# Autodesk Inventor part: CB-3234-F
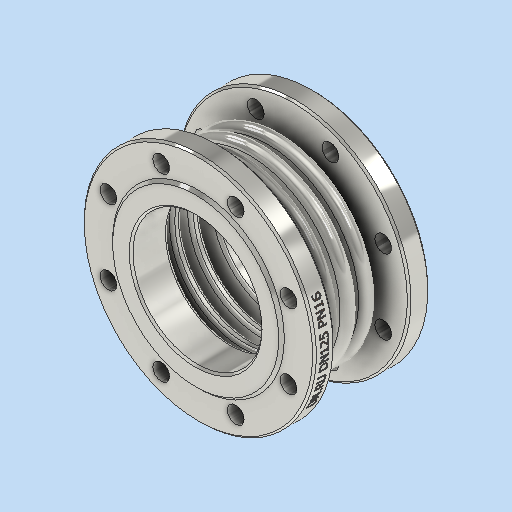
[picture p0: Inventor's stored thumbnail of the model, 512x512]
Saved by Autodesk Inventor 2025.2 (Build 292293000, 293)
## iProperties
Company: DN.RU
Created: 2026-04
Part Number: CB-3234-F
Material: Типовые
Document SubType Name: Modeling
Designer: DN.RU
Density: 6.05543 g/cm^3
Appearance: По умолчанию
Description: D140-02117
Mass: 10500 g
Surface Area: 4722.2 cm^2
Volume: 1733.98 cm^3
Author: DN.RU
Title: Компенсатор сильфонный осевой DN.ru Ду125 Ру16
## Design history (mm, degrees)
sketch "Эскиз1"
  geometry: L1 (0, 0)-(0, -65); L2 (77.5, -65)-(77.5, 0); L3 (77.5, 0)-(0, 0); L4 (77.5, 0)-(77.5, 0); L5 (57.5, 0)-(97.5, 0); L6 (57.5, -7)-(97.5, -7); L7 (97.5, 7)-(57.5, 7); L8 (97.5, -5)-(57.5, -5); L9 (57.5, 5)-(97.5, 5); L10 (97.5, -13)-(57.5, -13); L11 (57.5, -15)-(97.5, -15); L12 (57.5, -20)-(97.5, -20); L13 (57.5, -27)-(97.5, -27); L14 (97.5, -25)-(57.5, -25); L15 (0, -65)-(77.5, -65); L16 (77.5, -65)-(69.5, -65); L17 (69.5, -65)-(69.5, -25); L18 (77.5, -15)-(75.5, -15); L19 (75.5, -15)-(75.5, -5); L20 (77.5, 5)-(75.5, 5); L21 (75.5, 5)-(75.5, 0); L22 (0, -65)-(0, -40); L23 (0, -40)-(125, -40); L24 (125, -40)-(125, -65); L25 (125, -65)-(0, -65); L26 (77.5, -40)-(77.5, -55); L27 (77.5, -55)-(81.5, -55); L28 (81.5, -55)-(81.5, -40); L29 (81.5, -40)-(77.5, -40); L30 (77.5, 0)-(104.5, 0); A1 r 7 centre (57.5, 0) between (57.5, 7) and (57.5, -7); A2 r 7 centre (97.5, 0) between (97.5, -7) and (97.5, 7); A3 r 5 centre (57.5, 0) between (57.5, 5) and (57.5, -5); A4 r 5 centre (97.5, 0) between (97.5, -5) and (97.5, 5); A5 r 5 centre (57.5, -20) between (57.5, -15) and (57.5, -25); A6 r 7 centre (57.5, -20) between (57.5, -13) and (57.5, -27); A7 r 5 centre (97.5, -20) between (97.5, -25) and (97.5, -15); A8 r 7 centre (97.5, -20) between (97.5, -27) and (97.5, -13); 20 further points
  constraints: 64 end point, 17 point on circle, 14 point on line, 8 centre point, 7 parallel, 5 perpendicular, 4 tangent, 3 midpoint, 2 vertical, 1 horizontal, 25 other
  dimensions: "d0" = 65 distance of L1.start L1.end; "d3" = 0 distance of L2.end L4.end; "d4" = 20 distance of L4.end L5.end; "d5" = 14 diameter of A2; "d6" = 2 distance between parallel lines of L6 L8; "d9" = 20 distance of L4.end point (77.5, -20); "d18" = 2 distance of L18.start L18.end; "d19" = 2 distance of L20.start L20.end; "d27" = 69.5 distance between parallel lines of L1 L17; "d28" = 8 distance between parallel lines of L2 L17; "d29" = 25 distance of L1.end L22.end; "d30" = 125 distance of L22.end L23.end; "d31" = 15 distance of L26.start L26.end; "d32" = 4 distance of L27.end L26.end
revolve "Вращение1" sketch "Эскиз1" stored, may be unused: angle "d20" = 360 deg
sketch "Эскиз3" dims "d33" = 210
  geometry: L1 (0, 0)-(71.096, 29.449); L2 (0, 0)-(76.954, 0); C1 r 9 at (97.007, 40.182); C2 r 9 at (40.182, 97.007); C3 r 9 at (-40.182, 97.007); C4 r 9 at (-97.007, 40.182); C5 r 69.5 at (0, 0) reference; C6 r 92.5 at (0, 0); C7 r 125 at (0, 0) reference; C8 r 9 at (-97.007, -40.182); C9 r 9 at (-40.182, -97.007); C10 r 9 at (40.182, -97.007); C11 r 9 at (97.007, -40.182); 1 further point
  constraints: 9 centre point, 4 end point, 2 coincident, 1 equal length, 1 horizontal, 1 point on line, 20 other
  dimensions: "d34" = 22.5 deg angle of L2 L1; "d35" = 18 diameter of C1; "d38" = 360 deg dimension on point (0, 0) C1.centre (derived); "d40" = 185 diameter of C6
  node "Эскиз — круговой массив1" dims "d38" = 360 deg (derived)
extrude "Выдавливание1" cut sketch "Эскиз3" stored distance "d41" = 10; taper "d42" = 0 deg
extrude "Выдавливание2" cut sketch "Эскиз3" distance "d43" = 3; taper "d44" = 0 deg
chamfer "Фаска2" distance "d45" = 3; stored, may be unused: second distance "d46" = 2, angle "d47" = 45 deg
chamfer "Фаска3" distance "d48" = 2; stored, may be unused: second distance "d49" = 2, angle "d50" = 45 deg
mirror "Зеркальное отражение2"
fillet "Сопряжение2" dims "d51" = 3
node "РабПлоскость2"
sketch "Эскиз4"
  geometry: L1 (-60.476, 3.302)-(81.492, 3.302); L2 (81.492, 3.302)-(81.492, -37.818); L3 (81.492, -37.818)-(-60.476, -37.818); L4 (-60.476, -37.818)-(-60.476, 3.302); 1 further point
  constraints: 2 other
feature "Рельеф2" sketch "Эскиз4" dims "d52" = 0.1, "d53" = 0
feature "ɼ耀ɾ耀ʀ耀ʂ耀ʄ耀ʆ耀ʈ耀ʊ耀" dims "d0" = 65, "d3" = 0, "d4" = 20, "d5" = 14, "d6" = 2, "d7" = 20, "d9" = 20, "d10" = 10, "d12" = 10, "d18" = 2, "d19" = 2, "d20" = 360 deg, "d27" = 69.5, "d28" = 8, "d29" = 25, "d30" = 125, "d31" = 15, "d32" = 4, "d33" = 210, "d34" = 22.5 deg, "d35" = 18, "d36" = 80, "d38" = 360 deg (derived), "d40" = 185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
node "Твердое тело1"
node "Эскиз — прямоугольный массив1" dims "d9" = 20, "d12" = 10
